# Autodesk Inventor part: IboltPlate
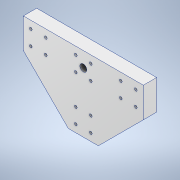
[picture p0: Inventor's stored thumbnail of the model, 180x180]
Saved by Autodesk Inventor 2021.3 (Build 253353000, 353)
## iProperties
Created: 2022-01
Part Number: IboltPlate
Material: アルミニウム 6061
Document SubType Name: Modeling
Designer: kengo
Density: 2.7 g/cm^3
Appearance: アルミニウム - フラット
Mass: 2209.1 g
Surface Area: 1042.69 cm^2
Volume: 818.186 cm^3
Author: kengo
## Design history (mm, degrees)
sketch "スケッチ1"
  geometry: L1 (-176.41, 74.202)-(48.59, 74.202); L2 (48.59, 74.202)-(48.59, -150.798); L3 (48.59, -150.798)-(-176.41, -150.798); L4 (-176.41, -150.798)-(-176.41, 74.202); 1 further point
  constraints: 8 end point, 2 parallel, 1 horizontal, 1 perpendicular
  dimensions: "d0" = 225 distance of L1.start L1.end; "d1" = 225 distance of L1.end L2.end
extrude "押し出し1" new body sketch "スケッチ1" distance "d2" = 40; taper "d3" = 0 deg
sketch "スケッチ2"
  geometry: L1 (-176.41, -150.798)-(48.59, -150.798) reference; L2 (-176.41, 74.202)-(-176.41, -150.798) reference; L3 (-176.41, -150.798)-(-41.41, -150.798); L4 (48.59, -150.798)-(48.59, 74.202) reference; L5 (-176.41, -150.798)-(-176.41, -15.798); L6 (48.59, 74.202)-(-176.41, 74.202) reference; L7 (-176.41, -15.798)-(-41.41, -150.798); 2 further points
  constraints: 6 end point, 1 horizontal, 1 point on line
  dimensions: "d4" = 90 distance from line of L4 L3.end; "d5" = 90 distance from line of L6 L5.end
extrude "押し出し2" cut sketch "スケッチ2" distance "d6" = 40; taper "d7" = 0 deg
sketch "スケッチ5"
  geometry: L1 (48.59, 74.202)-(228.59, 74.202); L2 (228.59, 74.202)-(228.59, -150.798); L3 (228.59, -150.798)-(48.59, -150.798); L4 (48.59, -150.798)-(48.59, 74.202); L5 (48.59, -150.798)-(48.59, 74.202) reference; L6 (48.59, 74.202)-(-176.41, 74.202) reference; L7 (-41.41, -150.798)-(48.59, -150.798) reference; 1 further point
  constraints: 8 end point, 2 parallel, 1 horizontal, 1 perpendicular
  dimensions: "d42" = 180 distance of L1.start L1.end; "d43" = 0 distance between parallel lines of L5 L4; "d44" = 0 distance between parallel lines of L6 L1; "d45" = 0 distance between parallel lines of L7 L3
extrude "押し出し3" join sketch "スケッチ5" distance "d46" = 40; taper "d47" = 0 deg
sketch "スケッチ3"
  geometry: L1 (48.59, 74.202)-(-176.41, 74.202) reference; L2 (-176.41, 74.202)-(-176.41, -15.798) reference; L3 (48.59, 74.202)-(-108.91, -83.298); L4 (-41.41, -150.798)-(-176.41, -15.798) reference; 9 further points
  constraints: 4 symmetric about line, 2 end point, 1 horizontal, 1 midpoint, 1 vertical, 3 other
  dimensions: "d8" = 22.5 distance from line of L1 point (-153.91, 51.702); "d9" = 22.5 distance from line of L2 point (-153.91, 51.702); "d12" = 45 distance of point (-153.91, 51.702) point (-108.91, 51.702); "d15" = 45 distance of point (-153.91, 51.702) point (-153.91, 6.702)
hole "穴1" sketch "スケッチ3" at (-153.91, 51.702), (-108.91, 51.702), (-153.91, 6.702), (-108.91, 6.702), (-18.91, -83.298), (-18.91, -128.298), (26.09, -83.298), (26.09, -128.298) diameter "d18" = 8; stored, may be unused: countersink angle "d22" = 90 deg, drill point angle "d24" = 0 deg; dims "d19" = 8, "d20" = 14, "d21" = 8, "d23" = 40
sketch "スケッチ4" dims "d53" = 10
  geometry: L1 (-48.59, -150.798)-(-48.59, 74.202) reference; L2 (-48.59, 74.202)-(176.41, 74.202) reference; 9 further points
  constraints: 2 horizontal, 1 vertical, 7 other
  dimensions: "d25" = 22.5 distance from line of L1 point (-26.09, 51.702); "d26" = 22.5 distance from line of L2 point (-26.09, 51.702); "d29" = 45 distance of point (-26.09, 51.702) point (18.91, 51.702); "d32" = 45 distance of point (-26.09, 51.702) point (-26.09, 6.702); "d50" = 135 distance of point (18.91, 6.702) point (-116.09, 6.702)
hole "穴2" sketch "スケッチ4" at (-26.09, 51.702), (18.91, 51.702), (-26.09, 6.702), (18.91, 6.702), (-116.09, 6.702), (-116.09, 51.702), (-161.09, 51.702), (-161.09, 6.702) diameter "d35" = 8; stored, may be unused: countersink angle "d39" = 90 deg, drill point angle "d41" = 0 deg; dims "d36" = 8, "d37" = 14, "d38" = 8, "d40" = 40
sketch "スケッチ6"
  geometry: L1 (228.59, 74.202)-(-176.41, 74.202) reference; L2 (183.59, 74.202)-(183.59, -150.411); L3 (183.59, -150.411)-(183.59, -150.411); L4 (-41.41, -150.798)-(228.59, -150.798) reference; L5 (48.59, -150.798)-(183.59, -15.798); L6 (228.59, -150.798)-(228.59, 74.202) reference; L7 (183.59, 74.202)-(228.59, 74.202); L8 (228.59, 74.202)-(228.59, -150.798); L9 (228.59, -150.798)-(183.59, -150.798); L10 (183.59, -150.798)-(183.59, 74.202); L11 (48.59, -150.798)-(183.59, -150.798); C1 r 4 at (161.09, 6.702) reference; 1 further point
  constraints: 16 end point, 4 point on line, 2 parallel, 1 horizontal, 1 perpendicular
  dimensions: "d55" = 45 deg angle of L4 L5; "d56" = 90 distance of L4.start L5.start; "d57" = 180 deg angle of L6 L2; "d58" = 22.5 distance from line of C1.centre L2
extrude "押し出し4" cut sketch "スケッチ6" distance "d59" = 40; taper "d60" = 0 deg
sketch "スケッチ7"
  geometry: C1 r 4 at (-18.91, 51.702) reference; 2 further points
  dimensions: "d61" = 22.5 horizontal distance of point (3.59, 29.202) C1.centre; "d62" = 22.5 horizontal distance of point (3.59, 29.202) C1.centre
hole "穴3" sketch "スケッチ7" at (3.59, 29.202) diameter "d63" = 20.752; stored, may be unused: countersink angle "d67" = 90 deg, drill point angle "d69" = 118 deg; dims "d64" = 40, "d65" = 4, "d66" = 2, "d68" = 61.1
node "ソリッド1"
